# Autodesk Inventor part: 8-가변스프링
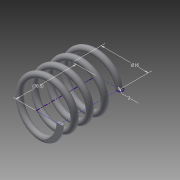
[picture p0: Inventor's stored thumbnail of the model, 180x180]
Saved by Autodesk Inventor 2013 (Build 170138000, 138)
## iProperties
Created: 2015-04
Part Number: 8-가변스프링
Material: 강철, 탄소
Document SubType Name: Modeling
Designer: Administrator
Density: 1 g/cm^3
Mass: 0.61834 g
Surface Area: 12.6017 cm^2
Volume: 0.61834 cm^3
Author: Administrator
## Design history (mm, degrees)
sketch "스케치1"
  geometry: L1 (0, 0)-(8, 0); L2 (8, 0)-(8, -20.5); L3 (8, -20.5)-(0, -20.5); L4 (0, -20.5)-(0, 0); C1 r 1 at (8, 0)
  constraints: 8 end point, 2 parallel, 1 centre point, 1 coincident, 1 horizontal, 1 perpendicular
  dimensions: "d0" = 16 diameter of L2 L4; "d2" = 20.49951 distance of L3.end L1.start (derived); "d3" = 2 diameter of C1
feature "코일1" sketch "스케치1" pitch "d4" = 10; turns "d6" = 4; dims "d5" = 20.49951 (= d2), "d7" = 0, angle "d8" = 90 deg, angle "d9" = 90 deg, "d10" = 0, "d11" = 0
sketch "스케치2"
  geometry: L1 (-7, 0)-(-9, 0) reference; 1 further point
  constraints: 1 horizontal alignment
extrude "돌출1" cut sketch "스케치2" stored distance "d12" = 10; taper "d13" = 0 deg
node "작업 평면1"
sketch "스케치3"
  geometry: L1 (9, 0)-(7, 0) reference; 1 further point
  constraints: 1 horizontal alignment
extrude "돌출2" cut sketch "스케치3" stored distance "d15" = 10; taper "d16" = 0 deg
node "솔리드1"
node "절단 모서리 투영1"
node "절단 모서리 투영2"
other parameters: "d14" = -20.49951 (= -d2)
